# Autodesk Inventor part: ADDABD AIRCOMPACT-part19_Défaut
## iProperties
Shininess: 64.0
Length Units: 11269
Angle Units: 11279
Time Units: 11290
Mass Units: 11283
Length Display Precision: 3
Angle Display Precision: 2
Compacted: True
Part Number: ADDABD AIRCOMPACT-part19_Défaut
Document SubType Name: Modeling
Created: 2006-01
Material: Par défaut
Designer: riri
Density: 0.0
Volumn: 0.0
Area: 0.0
PropertySet Name: Model Information
Control State: 0
Master: False
Checked Out: False
Author: riri
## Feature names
1. Base1
